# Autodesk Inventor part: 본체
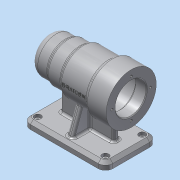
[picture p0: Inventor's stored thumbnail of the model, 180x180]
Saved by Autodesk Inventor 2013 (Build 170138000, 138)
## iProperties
Created: 2016-06
Part Number: 본체
Material: 알루미늄 6061
Document SubType Name: Modeling
Designer: dgall
Density: 2.71 g/cm^3
Mass: 683.705 g
Surface Area: 644.215 cm^2
Volume: 252.29 cm^3
Author: dgall
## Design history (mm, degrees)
sketch "스케치1"
  geometry: L1 (-56, 25)-(-31, 25); L2 (-31, 25)-(-31, 27); L3 (-31, 27)-(-11, 27); L4 (-11, 27)-(-11, 30); L5 (-11, 30)-(28, 30); L6 (28, 30)-(28, 34); L7 (28, 34)-(56, 34); L8 (56, 34)-(56, 0); L9 (56, 0)-(-56, 0); L10 (-56, 0)-(-56, 25); 2 further points
  constraints: 20 end point, 5 parallel, 2 horizontal, 2 vertical, 1 coincident, 1 midpoint, 1 perpendicular
  dimensions: "d0" = 68 diameter of L7 L9; "d2" = 50 diameter of L1 L9; "d3" = 54 diameter of L3 L9; "d4" = 60 diameter of L5 L9; "d5" = 25 distance of L1.start L1.end; "d6" = 45 distance from line of L4.end L10; "d7" = 84 distance from line of L6.end L10; "d8" = 112 distance between parallel lines of L8 L10
revolve "회전1" sketch "스케치1" stored, may be unused: angle "d9" = 90 deg
node "작업 평면1"
sketch "스케치2"
  geometry: L1 (-56, 35)-(56, 35); L2 (56, 35)-(56, -35); L3 (56, -35)-(-56, -35); L4 (-56, -35)-(-56, 35); 3 further points
  constraints: 8 end point, 2 midpoint, 2 parallel, 1 horizontal, 1 horizontal alignment, 1 perpendicular, 1 vertical alignment
  dimensions: "d11" = 112 distance of L1.start L1.end; "d13" = 70 distance of L1.end L2.end
extrude "돌출1" join sketch "스케치2" distance "d14" = 10; taper "d15" = 0 deg
sketch "스케치5"
  geometry: L1 (-56, 35)-(-56, -35) reference; L2 (-36, 4)-(36, 4); L3 (36, 4)-(36, -4); L4 (36, -4)-(-36, -4); L5 (-36, -4)-(-36, 4); 3 further points
  constraints: 8 end point, 2 midpoint, 2 parallel, 1 horizontal, 1 horizontal alignment, 1 perpendicular, 1 vertical alignment
  dimensions: "d24" = 20 distance between parallel lines of L1 L5; "d25" = 8 distance of L4.end L2.start
extrude "돌출3" join sketch "스케치5" stored distance "d26" = 8; taper "d27" = 0 deg
fillet "모깎기2" dims "d80" = 10
sketch "스케치6"
  geometry: L1 (-4, -60)-(-4, -24.678) reference; L2 (35, -60)-(-35, -60) reference; L3 (-28, -60)-(-15.509, -25.68); L4 (-35, -70)-(-35, -60) reference; A1 r 30 centre (0, 0) between (4, -29.732) and (-4, -29.732) reference; 1 further point
  constraints: 2 end point, 1 point on circle, 1 point on line
  dimensions: "d28" = 7 distance from line of L4 L3.start; "d29" = 110 deg angle of L2 L3
feature "리브1" sketch "스케치6" dims "d30" = 1, "d31" = 8, "d32" = 0, "d33" = 0, "d34" = 1, "d35" = 1
sketch "스케치7"
  geometry: L1 (31, 25)-(56, 25) reference; L2 (56, 25)-(56, -25) reference; L3 (56, -25)-(36, -25) reference; L4 (36, -25)-(36, -60) reference; L5 (36, -60)-(56, -60) reference; L6 (56, -60)-(56, -70) reference; L7 (56, -70)-(-56, -70) reference; L8 (-56, -70)-(-56, -60) reference; L9 (-56, -60)-(-36, -60) reference; L10 (-36, -60)-(-36, -34) reference; L11 (-36, -34)-(-56, -34) reference; L12 (-56, -34)-(-56, 34) reference; L13 (-56, 34)-(-28, 34) reference; L14 (-28, 34)-(-28, 30) reference; L15 (-28, 30)-(11, 30) reference; L16 (11, 30)-(11, 27) reference; L17 (11, 27)-(31, 27) reference; L18 (31, 27)-(31, 25) reference; L19 (25, 17.5)-(25, 21); L20 (13, 24)-(-41, 24); L21 (43, 17.5)-(43, 16); L22 (43, 16)-(47, 16); L23 (47, 16)-(47, 10.5); L24 (47, 10.5)-(50, 10.5); L25 (50, 10.5)-(50, 0); L26 (13, 21)-(25, 21); L27 (13, 24)-(13, 21); L28 (-41, 21)-(-56, 21); L29 (-41, 24)-(-41, 21); L30 (50, 0)-(-56, 0); L31 (25, 17.5)-(43, 17.5); 1 further point
  constraints: 26 end point, 5 perpendicular, 4 parallel, 3 vertical alignment, 1 horizontal, 1 horizontal alignment, 1 midpoint, 1 point on line
  dimensions: "d45" = 3 distance of L23.end L24.end; "d48" = 12 distance of L26.start L19.end; "d51" = 15 distance of L28.start L28.end; "d52" = 54 distance of L20.start L20.end; "d53" = 42 diameter of L28 L30; "d54" = 48 diameter of L20 L30; "d55" = 42 diameter of L26 L30; "d56" = 35 diameter of L31 L30; "d57" = 32 diameter of L22 L30; "d58" = 21 diameter of L24 L30; "d59" = 18 distance of L19.start L21.start; "d60" = 4 distance of L21.end L22.end
revolve "회전2" sketch "스케치7" stored, may be unused: angle "d61" = 90 deg
sketch "스케치8"
  geometry: C1 r 21 at (0, 0) reference; 1 further point
  constraints: 1 vertical alignment
  dimensions: "d62" = 26 distance of point (0, 26) C1.centre
hole "구멍1" sketch "스케치8" at (0, 26) diameter "d63" = 3.242; stored, may be unused: countersink angle "d67" = 90 deg, drill point angle "d69" = 118 deg; dims "d64" = 8, "d65" = 4, "d66" = 2, "d68" = 11
node "작업 평면2"
sketch "스케치9"
  geometry: L1 (47.5, -34)-(47.5, 34) reference; 2 further points
  constraints: 1 horizontal alignment, 1 other
  dimensions: "d73" = 48 distance from line of point (-0.5, 0) L1
feature "엠보싱1" sketch "스케치9" dims "d0" = 68, "d2" = 50, "d3" = 54, "d4" = 60, "d5" = 25, "d6" = 45, "d7" = 84, "d8" = 112, "d74" = 0.5, "d75" = 0
chamfer "모따기1" distance "d76" = 4; stored, may be unused: second distance "d77" = 2, angle "d78" = 45 deg
fillet "모깎기1" dims "d79" = 10
sketch "스케치11"
  geometry: A1 r 6 centre (46, -25) between (46, -31) and (52, -25) reference; A2 r 6 centre (46, 25) between (52, 25) and (46, 31) reference; A3 r 6 centre (-46, 25) between (-46, 31) and (-52, 25) reference; A4 r 6 centre (-46, -25) between (-52, -25) and (-46, -31) reference; 1 further point
hole "구멍2" sketch "스케치11" at (-46, -25), (46, -25), (46, 25), (-46, 25) diameter "d81" = 5; stored, may be unused: countersink angle "d85" = 90 deg, drill point angle "d87" = 118 deg; dims "d82" = 8, "d83" = 9, "d84" = 4, "d86" = 11
fillet "모깎기3" dims "d88" = 0.3
chamfer "모따기2" distance "d89" = 1; stored, may be unused: second distance "d90" = 2, angle "d91" = 45 deg
fillet "모깎기7" dims "d95" = 3
fillet "모깎기4" dims "d92" = 3
fillet "모깎기5" dims "d93" = 3
fillet "모깎기6" dims "d94" = 3
fillet "모깎기8" dims "d96" = 3
node "솔리드1"
mirror "대칭1"
pattern_circular "원형 패턴1" dims angle "d71" = 360 deg
node "절단 모서리 투영1"
